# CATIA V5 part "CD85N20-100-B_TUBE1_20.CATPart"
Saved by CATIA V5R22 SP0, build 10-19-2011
Part number: CD85N20-100-B_TUBE1_20
Revision: ANY
Definition: UNKNOWN
Nomenclature: CD85N20-100-B_TUBE1_20
Source: Unknown
Bounding box of the stored display mesh (mm): x -10.8 to 10.8, y -10.8 to 10.79, z -66 to 66
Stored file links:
  D:\PER\CAO_PER_MODIF_2025\CAO_PER_pick&place_2024P\Sous_Ensemble_Flacon\CD85N20-100-B_TUBE1_20.CATPart
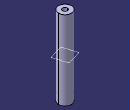
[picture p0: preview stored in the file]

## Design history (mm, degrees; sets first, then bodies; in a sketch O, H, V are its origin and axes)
Set1
  Plane1: type Offset, RefPlane DatumSurface1, Offset 66, reversed
  DatumSurface1
Body1 "CHAMBER" (main body)
  Solid1: solid without history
